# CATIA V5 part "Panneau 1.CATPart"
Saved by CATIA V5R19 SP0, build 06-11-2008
Part number: Panneau 1
Bounding box of the stored display mesh (mm): x -170.879 to 5.629, y -100 to 100, z -69.266 to -56.223
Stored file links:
  G:\EU_thinkMotion\CFAO_2010\St2M_groupe2\St2M_groupe2\csayed\csayed\csayed\Panneau 1.CATPart
  G:\EU_thinkMotion\CFAO_2010\St2M_groupe2\St2M_groupe2\csayed\csayed\csayed\Structure Trappe.CATPart
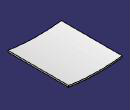
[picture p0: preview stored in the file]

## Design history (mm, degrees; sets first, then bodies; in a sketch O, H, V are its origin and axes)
Body1 (main body)
  Sketch1 on zx-plane, origin (0, 0, 0), H (-1, 0, 0), V (0, 0, 1)
    spline S1 through (-5.6287, -56.2229) (77.8259, -64.1522) (170.8786, -59.9149)
    spline S2 through (-5.6287, -61.2229) (77.8259, -69.1522) (170.8786, -64.9149)
    line L1 (-5.6287, -56.2229) -> (-5.6287, -61.2229)
    point P1 (-5.6287, -61.2229)
    point P2 (-5.6287, -56.2229)
    line L2 (170.8786, -59.9149) -> (170.8786, -64.9149)
    point P3 (170.8786, -59.9149)
    point P4 (170.8786, -64.9149)
    point P5 (-5.6287, -56.2229)
    point P6 (-5.6287, -61.2229)
    point P7 (77.8259, -64.1522)
    point P8 (77.8259, -69.1522)
    point P9 (170.8786, -59.9149)
    point P10 (170.8786, -64.9149)
    distance P5 P6 = 5
    distance P7 P8 = 5
    coincidence: P6 P1, P2 S1, P5 P2, P9 P3, P10 P4
    vertical: L1 V, L2 V
  Pad1: profile Sketch1, direction (0, 1, 0), length 100, mirrored extent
